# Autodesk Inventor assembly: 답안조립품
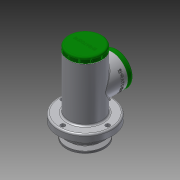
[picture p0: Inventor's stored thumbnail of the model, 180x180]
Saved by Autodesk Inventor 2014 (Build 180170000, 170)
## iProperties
Created: 2016-08
Part Number: 답안조립품
Document SubType Name: Assembly
Designer: USER
Author: USER
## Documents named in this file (25)
- C:\Users\USER\Desktop\460807V1007\답안조립품.iam
- C:\Users\USER\Desktop\460807V1007\본체.ipt
- C:\Users\USER\Desktop\460807V1007\V-벨트풀리.ipt
- C:\Users\USER\Desktop\460807V1007\너트 M10.ipt
- C:\Users\USER\Desktop\460807V1007\링크.ipt
- C:\Users\USER\Desktop\460807V1007\멈춤링 15 x 1.ipt
- C:\Users\USER\Desktop\460807V1007\멈춤링 35x1.6.ipt
- C:\Users\USER\Desktop\460807V1007\베어링 15 x 35 x 11.ipt
- C:\Users\USER\Desktop\460807V1007\볼트 M4 x 10.ipt
- C:\Users\USER\Desktop\460807V1007\볼트 M4 x 12.ipt
- C:\Users\USER\Desktop\460807V1007\부시1.ipt
- C:\Users\USER\Desktop\460807V1007\부시2.ipt
- C:\Users\USER\Desktop\460807V1007\분할핀 1.6 x 12.ipt
- C:\Users\USER\Desktop\460807V1007\사이드 커버.ipt
- 사이드 커버.ipt
- C:\Users\USER\Desktop\460807V1007\슬라이더.ipt
- C:\Users\USER\Desktop\460807V1007\오일 실 15 25 7.ipt
- C:\Users\USER\Desktop\460807V1007\와셔 4x16.ipt
- C:\Users\USER\Desktop\460807V1007\와셔 10x21.ipt
- C:\Users\USER\Desktop\460807V1007\클래스터 핀 6 x 24.ipt
- C:\Users\USER\Desktop\460807V1007\키 4 x 4 x 18.ipt
- C:\Users\USER\Desktop\460807V1007\탑 부시.ipt
- C:\Users\USER\Desktop\460807V1007\탑 커버.ipt
- 탑 커버.ipt
- C:\Users\USER\Desktop\460807V1007\편심축.ipt
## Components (6 placed, 3 different names)
1. V-벨트풀리:1
2. ISO 4017 M4 x 10:2
3. ISO 4762 M4 x 12:2
4. ISO 4762 M4 x 12:3
5. ISO 4762 M4 x 12:4
6. ISO 4762 M4 x 12:5
